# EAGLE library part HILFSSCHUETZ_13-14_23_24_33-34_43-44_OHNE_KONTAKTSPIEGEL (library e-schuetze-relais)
Hilfsschütz mit 4 Schließern ohne Kontaktspiegel
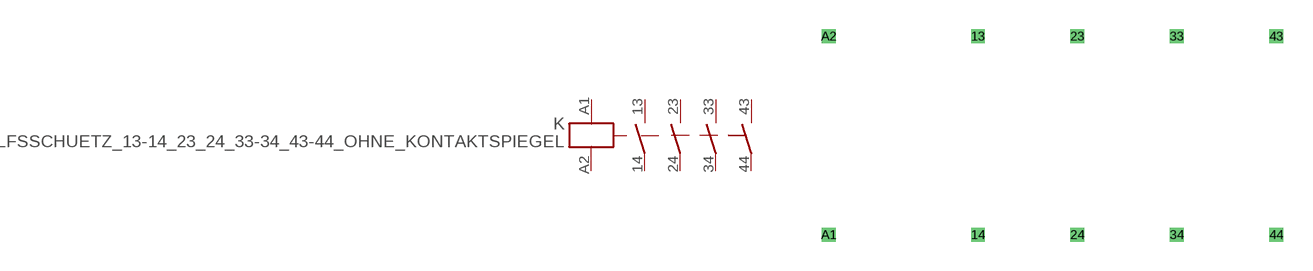
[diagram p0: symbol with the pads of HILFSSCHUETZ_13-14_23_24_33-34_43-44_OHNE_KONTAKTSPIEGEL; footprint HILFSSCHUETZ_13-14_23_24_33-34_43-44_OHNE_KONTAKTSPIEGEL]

Designator prefix K

## HILFSSCHUETZ_13-14_23_24_33-34_43-44_OHNE_KONTAKTSPIEGEL  [HILFSSCHUETZ_13-14_23_24_33-34_43-44_OHNE_KONTAKTSPIEGEL]
13  13  pas
14  14  pas
23  23  pas
24  24  pas
33  33  pas
34  34  pas
43  43  pas
44  44  pas
A1  A1  in
A2  A2  in

## Footprint HILFSSCHUETZ_13-14_23_24_33-34_43-44_OHNE_KONTAKTSPIEGEL (pad centres in mm)
Dummy
drill 0.2 pad 0.6 square: 13 7.62,5.08; 14 7.62,-5.08; 23 12.7,5.08; 24 12.7,-5.08; 33 17.78,5.08; 34 17.78,-5.08; 43 22.86,5.08; 44 22.86,-5.08; A1 0,-5.08; A2 0,5.08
